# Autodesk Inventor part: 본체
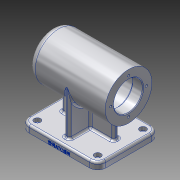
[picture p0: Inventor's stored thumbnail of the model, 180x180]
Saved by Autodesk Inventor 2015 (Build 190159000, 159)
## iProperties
Created: 2020-10
Part Number: 본체
Material: 알루미늄 6061
Document SubType Name: Modeling
Designer: Line503_02
Density: 2.7 g/cm^3
Appearance: 알루미늄 - 평지
Mass: 1026.28 g
Surface Area: 757.984 cm^2
Volume: 380.103 cm^3
Author: Line503_02
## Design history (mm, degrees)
sketch "스케치1"
  geometry: L1 (0, 0)-(112, 0); L2 (112, 0)-(112, 21); L3 (112, 21)-(97, 21); L4 (97, 21)-(97, 24); L5 (97, 24)-(43, 24); L6 (31, 21)-(31, 17.5); L7 (31, 17.5)-(13, 17.5); L8 (13, 17.5)-(13, 16); L9 (43, 24)-(43, 21); L10 (43, 21)-(31, 21); L11 (13, 16)-(9, 16); L12 (9, 16)-(9, 10.5); L13 (9, 10.5)-(6, 10.5); L14 (6, 10.5)-(6, 0); L15 (112, 0)-(112, 34); L16 (112, 34)-(0, 34); L17 (0, 34)-(0, 0)
  constraints: 34 end point, 11 perpendicular, 3 horizontal, 2 vertical, 1 point on line
  dimensions: "d0" = 112 distance of L1.start L1.end; "d1" = 15 distance between parallel lines of L4 L2; "d2" = 54 distance between parallel lines of L9 L4; "d3" = 12 distance between parallel lines of L6 L9; "d4" = 18 distance between parallel lines of L8 L6; "d5" = 4 distance between parallel lines of L12 L8; "d6" = 3 distance of L12.end L13.end; "d7" = 42 diameter of L3 L1; "d8" = 48 diameter of L5 L1; "d9" = 42 diameter of L10 L1; "d10" = 35 diameter of L7 L1; "d11" = 32 diameter of L11 L1; "d12" = 21 diameter of L13 L1; "d13" = 68 diameter of L16 L1
revolve "회전1" sketch "스케치1" stored, may be unused: angle "d14" = 90 deg
fillet "모깎기1" dims "d15" = 3
fillet "모깎기2" dims "d16" = 0.3
fillet "모깎기3" dims "d17" = 10
node "작업 평면1"
sketch "스케치2"
  geometry: L1 (0, 0)-(0, 45); L2 (0, 0)-(0, -45); L3 (0, -45)-(-112, -45); L4 (-112, -45)-(-112, 45); L5 (-112, 45)-(0, 45)
  constraints: 10 end point, 2 vertical, 1 horizontal, 1 point on line
  dimensions: "d19" = 45 distance of L1.start L1.end; "d20" = 45 distance of L1.start L2.end; "d21" = 112 distance of L2.end L3.end; "d22" = 90 distance of L3.end L4.end
extrude "돌출1" join sketch "스케치2" distance "d23" = 10; taper "d24" = 0 deg
fillet "모깎기4" dims "d25" = 12
sketch "스케치3"
  geometry: L1 (100, -64)-(112, -64) reference; L2 (0, -64)-(12, -64) reference; L3 (112, -64)-(94, -64); L4 (94, -64)-(94, -34) reference; L5 (0, -64)-(18, -64); L6 (18, -64)-(18, -34); L7 (18, -34)-(18, -32.927); L8 (18, -32.927)-(94, -32.927) reference; L9 (94, -32.927)-(94, -34); L10 (18, -64)-(94, -64); 1 further point
  constraints: 16 end point, 2 perpendicular, 2 vertical, 1 collinear, 1 horizontal
  dimensions: "d26" = 18 distance of L1.end L3.end; "d27" = 18 distance of L2.start L5.end; "d66" = 30 distance from line of L4.end L1; "d67" = 30 distance from line of L6.end L1
extrude "돌출2" join sketch "스케치3" stored distance "d28" = 8; taper "d29" = 0 deg
node "작업 평면2"
sketch "스케치4"
  geometry: L1 (-64, 33)-(-64, -33) reference; L2 (-64, 45)-(-64, 33) reference; L3 (-64, -33)-(-64, -45) reference; L4 (-64, 0)-(-64, 34); L5 (-64, 34)-(0, 34); L6 (-64, 0)-(-64, -34); L7 (-64, -34)-(0, -34); A1 r 34 centre (0, 0) between (0, 34) and (0, -34) reference; A2 r 34 centre (0, 0) between (0, 34) and (0, -34); 1 further point
  constraints: 8 end point, 4 point on circle, 2 perpendicular, 2 point on line, 1 centre point, 1 coincident, 1 midpoint
  dimensions: "d31" = 34 distance of L4.start L4.end; "d32" = 34 distance of L4.start L6.end
extrude "돌출3" join sketch "스케치4" stored distance "d33" = 8; taper "d34" = 0 deg
fillet "모깎기5" dims "d35" = 3
fillet "모깎기6" dims "d36" = 3
fillet "모깎기7" dims "d38" = 3
sketch "스케치5"
  geometry: C1 r 34 at (0, 0) reference; 2 further points
  constraints: 1 vertical alignment
  dimensions: "d40" = 26 distance of point (0, 0) point (0, 26)
hole "구멍1" sketch "스케치5" at (0, 26) diameter "d41" = 3.242; stored, may be unused: countersink angle "d45" = 90 deg, drill point angle "d47" = 118 deg; dims "d42" = 8, "d43" = 4, "d44" = 2, "d46" = 11
sketch "스케치6"
  geometry: L1 (100, 45)-(12, 45) reference; L2 (112, -33)-(112, 33) reference; L3 (12, -45)-(100, -45) reference; L4 (0, 33)-(0, -33) reference; A1 r 12 centre (12, 33) between (12, 45) and (0, 33) reference; A2 r 12 centre (100, 33) between (112, 33) and (100, 45) reference; A3 r 12 centre (100, -33) between (100, -45) and (112, -33) reference; A4 r 12 centre (12, -33) between (0, -33) and (12, -45) reference; 5 further points
  constraints: 4 coincident
hole "구멍2" sketch "스케치6" at (12, 33), (12, -33), (100, -33), (100, 33) diameter "d51" = 5.5; stored, may be unused: countersink angle "d55" = 90 deg, drill point angle "d57" = 0 deg; dims "d52" = 5.5, "d53" = 9.5, "d54" = 5.4, "d56" = 10
fillet "모깎기8" dims "d58" = 3
chamfer "모따기1" distance "d59" = 1; stored, may be unused: second distance "d60" = 2, angle "d61" = 45 deg
sketch "스케치7"
  geometry: L1 (100, 0)-(100, 7) reference; L2 (0, 0)-(88, 0) reference; 2 further points
  constraints: 1 other
  dimensions: "d62" = 56 distance from line of L1 point (44, 3); "d63" = 3 distance from line of L2 point (44, 3)
feature "엠보싱1" sketch "스케치7" dims "d16" = 0.3, "d64" = 0.5, "d65" = 0
node "솔리드1"
pattern_circular "원형 패턴1" dims angle "d49" = 360 deg
node "투영된 루프1"
other parameters: "d18" = -74, "d30" = 56
